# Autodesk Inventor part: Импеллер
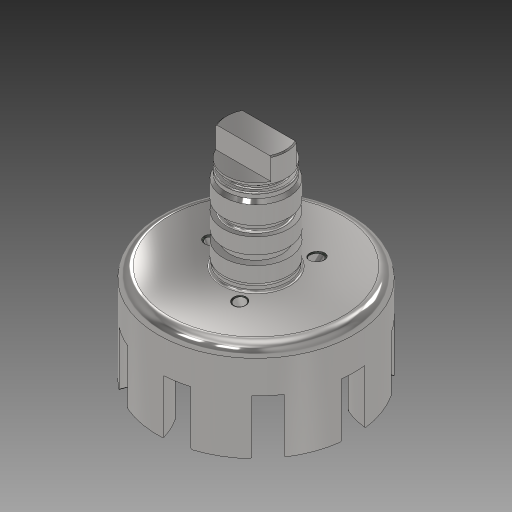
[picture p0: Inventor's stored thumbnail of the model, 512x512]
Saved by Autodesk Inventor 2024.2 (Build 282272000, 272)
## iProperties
Created: 2024-05
Part Number: Импеллер
Material: Сталь
Document SubType Name: Modeling
Designer: Алексей Бочаров
Density: 7.85 g/cm^3
Appearance: Листовая
Mass: 1486.65 g
Surface Area: 353.373 cm^2
Volume: 189.383 cm^3
Author: Алексей Бочаров
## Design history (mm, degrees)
sketch "Эскиз1"
  geometry: L1 (0, 0)-(-15, 0); L2 (-15, 0)-(-15, 53); L3 (-15, 53)-(0, 53); L4 (0, 53)-(0, 0); L5 (-15, 26.7)-(-12, 26.7); L6 (-12, 26.7)-(-12, 22.2); L7 (-12, 22.2)-(-15, 22.2); L8 (-15, 22.2)-(-15, 26.7); L9 (-15, 3.62)-(-14.7, 2.5); L10 (-14.7, 2.5)-(-14.7, 0); L11 (-15, 35)-(-14, 36.732); L12 (-14, 36.732)-(-14, 39); L13 (-14, 39)-(-11.5, 39); L14 (-11.5, 39)-(-11.5, 41.5); L15 (-11.5, 41.5)-(-14, 41.5); L16 (-14, 41.5)-(-14, 53); L17 (0, 0)-(-44.95, 0); L18 (-44.95, 0)-(-44.95, -45); L19 (-44.95, -45)-(0, -45); L20 (0, -45)-(0, 0); 5 further points
  constraints: 40 end point, 7 parallel, 7 perpendicular, 6 point on line, 3 horizontal, 2 midpoint, 2 vertical
  dimensions: "d2" = 30 diameter of L2 L4; "d3" = 53 distance from line of point (-7.5, 0) L3; "d4" = 4.5 distance between parallel lines of L7 L5; "d5" = 24 diameter of point (-12, 24.45) L4; "d6" = 22.2 distance between parallel lines of L1 L7; "d7" = 29.4 diameter of L10 L4; "d9" = 15 deg angle of L2 L9; "d10" = 35 distance from line of L11.start L1; "d12" = 23 diameter of L14 L4; "d14" = 2.5 distance between parallel lines of L13 L15; "d15" = 11.5 distance between parallel lines of L3 L15; "d16" = 28 diameter of L12 L4; "d17" = 45 distance between parallel lines of L17 L19; "d18" = 89.9 diameter of L18 L4; "d64" = 2.5 distance of L9.end L10.end; "d65" = 30 deg angle of L2 L11
revolve "Вращение1" sketch "Эскиз1" stored, may be unused: angle "d19" = 90 deg
sketch "Эскиз2"
  geometry: L1 (-14, 53)-(-14, 41.5) reference; L2 (-14, 53)-(14, 53) reference; L3 (14, 53)-(14, 41.5) reference; L4 (-14, 53)-(-5.85, 53); L5 (-5.85, 53)-(-5.85, 43); L6 (-5.85, 43)-(-14, 43); L7 (-14, 43)-(-14, 53); L8 (14, 53)-(5.85, 53); L9 (5.85, 53)-(5.85, 43); L10 (5.85, 43)-(14, 43); L11 (14, 43)-(14, 53); 5 further points
  constraints: 16 end point, 4 parallel, 2 collinear, 2 horizontal, 2 perpendicular
  dimensions: "d20" = 10 distance of L4.end L5.end; "d21" = 11.7 distance between parallel lines of L9 L5
extrude "Выдавливание1" cut sketch "Эскиз2" extent not by distance; stored distance "d22" = 0; taper "d23" = 0 deg
sketch "Эскиз3"
  geometry: L1 (0, 35)-(0, 44.95); L2 (-7.203, 36.473)-(9.175, 81.473); L3 (28.962, 23.31)-(47.297, 73.685); L4 (0, 0)-(15.374, 42.239); A1 r 35 centre (0, 0) between (0, 35) and (-8.2, 34.026); A2 r 44.95 centre (0, 0) between (0, 44.95) and (-5.3, 44.636) reference; A3 r 35 centre (-40.092, 48.444) between (-8.2, 34.026) and (-5.3, 44.636); A4 r 35 centre (40.092, 48.444) between (5.3, 44.636) and (8.2, 34.026); A5 r 35 centre (-61.852, 11.339) between (-28.153, 20.794) and (-32.752, 30.787); A6 r 35 centre (-0.427, 62.881) between (-24.632, 37.6) and (-15.59, 31.336); A7 r 35 centre (-54.67, -31.071) between (-34.933, -2.167) and (-44.879, 2.532); A8 r 35 centre (-40.746, 47.895) between (-43.038, 12.971) and (-32.085, 13.984); A9 r 35 centre (-21.908, -58.943) between (-25.367, -24.114) and (-36.006, -26.908); A10 r 35 centre (-62, 10.499) between (-41.306, -17.728) and (-33.567, -9.912); A11 r 35 centre (21.106, -59.235) between (-3.932, -34.778) and (-10.286, -43.757); A12 r 35 centre (-54.243, -31.81) between (-20.247, -40.132) and (-19.343, -29.169); A13 r 35 centre (54.243, -31.81) between (19.343, -29.169) and (20.247, -40.132); A14 r 35 centre (-21.106, -59.235) between (10.286, -43.757) and (3.932, -34.778); A15 r 35 centre (62, 10.499) between (33.567, -9.912) and (41.306, -17.728); A16 r 35 centre (21.908, -58.943) between (36.006, -26.908) and (25.367, -24.114); A17 r 35 centre (40.746, 47.895) between (32.085, 13.984) and (43.038, 12.971); A18 r 35 centre (54.67, -31.071) between (44.879, 2.532) and (34.933, -2.167); A19 r 35 centre (0.427, 62.881) between (15.59, 31.336) and (24.632, 37.6); A20 r 35 centre (61.852, 11.339) between (32.752, 30.787) and (28.153, 20.794); 44 further points
  constraints: 44 point on circle, 19 centre point, 8 end point, 3 symmetric about line, 2 parallel, 2 tangent, 1 coincident, 1 vertical, 1 vertical alignment, 84 other
  dimensions: "d24" = 70 diameter of A1; "d25" = 10.6 diameter of A2.end L1; "d26" = 16.4 diameter of A1.end L1; "d29" = 35 radius of A3; "d32" = 360 deg dimension on point (0, 0) A3.centre (derived); "d36" = 38.48649 distance between parallel lines of L2 L3 (derived)
extrude "Выдавливание2" cut sketch "Эскиз3" distance "d34" = 25; taper "d35" = 0 deg
sketch "Эскиз5" dims "d40" = 18
  geometry: 3 further points
  constraints: 2 vertical alignment, 1 coincident, 2 other
sketch "Эскиз8"
  geometry: L1 (-20, 0)-(0, 0); L2 (-20, -9)-(0, -20.547)
  constraints: 4 end point, 1 horizontal, 1 vertical alignment
  dimensions: "d47" = 30 deg angle of L1 L2
node "РабПлоскость2"
sketch "Эскиз9"
  geometry: C1 r 2.5 at (0, 0); 2 further points
  constraints: 1 centre point, 1 coincident
  dimensions: "d48" = 5 diameter of C1
extrude "Выдавливание4" cut sketch "Эскиз9" extent not by distance; stored distance "d49" = 0; taper "d50" = 0 deg
sketch "для проверки"
  geometry: 5 further points; 1 other entity
  constraints: 4 vertical alignment, 2 other
pattern_circular "Круговой массив2" dims angle "d52" = 360 deg
fillet "Сопряжение1" dims "d54" = 5, "d55" = 1, "d56" = 0.5, "d57" = 1
chamfer "Фаска1" distance "d58" = 0.5; stored, may be unused: second distance "d59" = 2, angle "d60" = 45 deg
chamfer "Фаска2" distance "d61" = 0.5; stored, may be unused: second distance "d62" = 2, angle "d63" = 45 deg
chamfer "Фаска3" distance "d66" = 0.5; stored, may be unused: second distance "d67" = 2, angle "d68" = 45 deg
sketch "Эскиз11"
  geometry: L1 (5.85, 43)-(14, 43) reference; L2 (15, 22.2)-(15, 3.62) reference; L3 (15, 10.7)-(11.95, 10.7); L4 (11.95, 10.7)-(11.95, 15); L5 (11.95, 15)-(15, 15); L6 (0, -64.606)-(0, 72.601) reference; 2 further points
  constraints: 6 end point, 2 perpendicular, 2 point on line, 1 horizontal, 1 midpoint
  dimensions: "d69" = 28 distance between parallel lines of L5 L1; "d70" = 4.3 distance from line of L5 point (13.475, 10.7); "d71" = 23.9 diameter of L4 L6
revolve "Вращение2" sketch "Эскиз11" stored, may be unused: angle "d72" = 90 deg
node "Твердое тело1"
